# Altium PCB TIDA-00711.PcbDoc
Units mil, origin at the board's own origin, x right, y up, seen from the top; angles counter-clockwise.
Board outline 1889.76 x 1574.8 mil, 2 copper layers (Top Layer, Bottom Layer), stack 64.8 mil thick; 57 components, 26 nets, 126 pads, 115 vias.
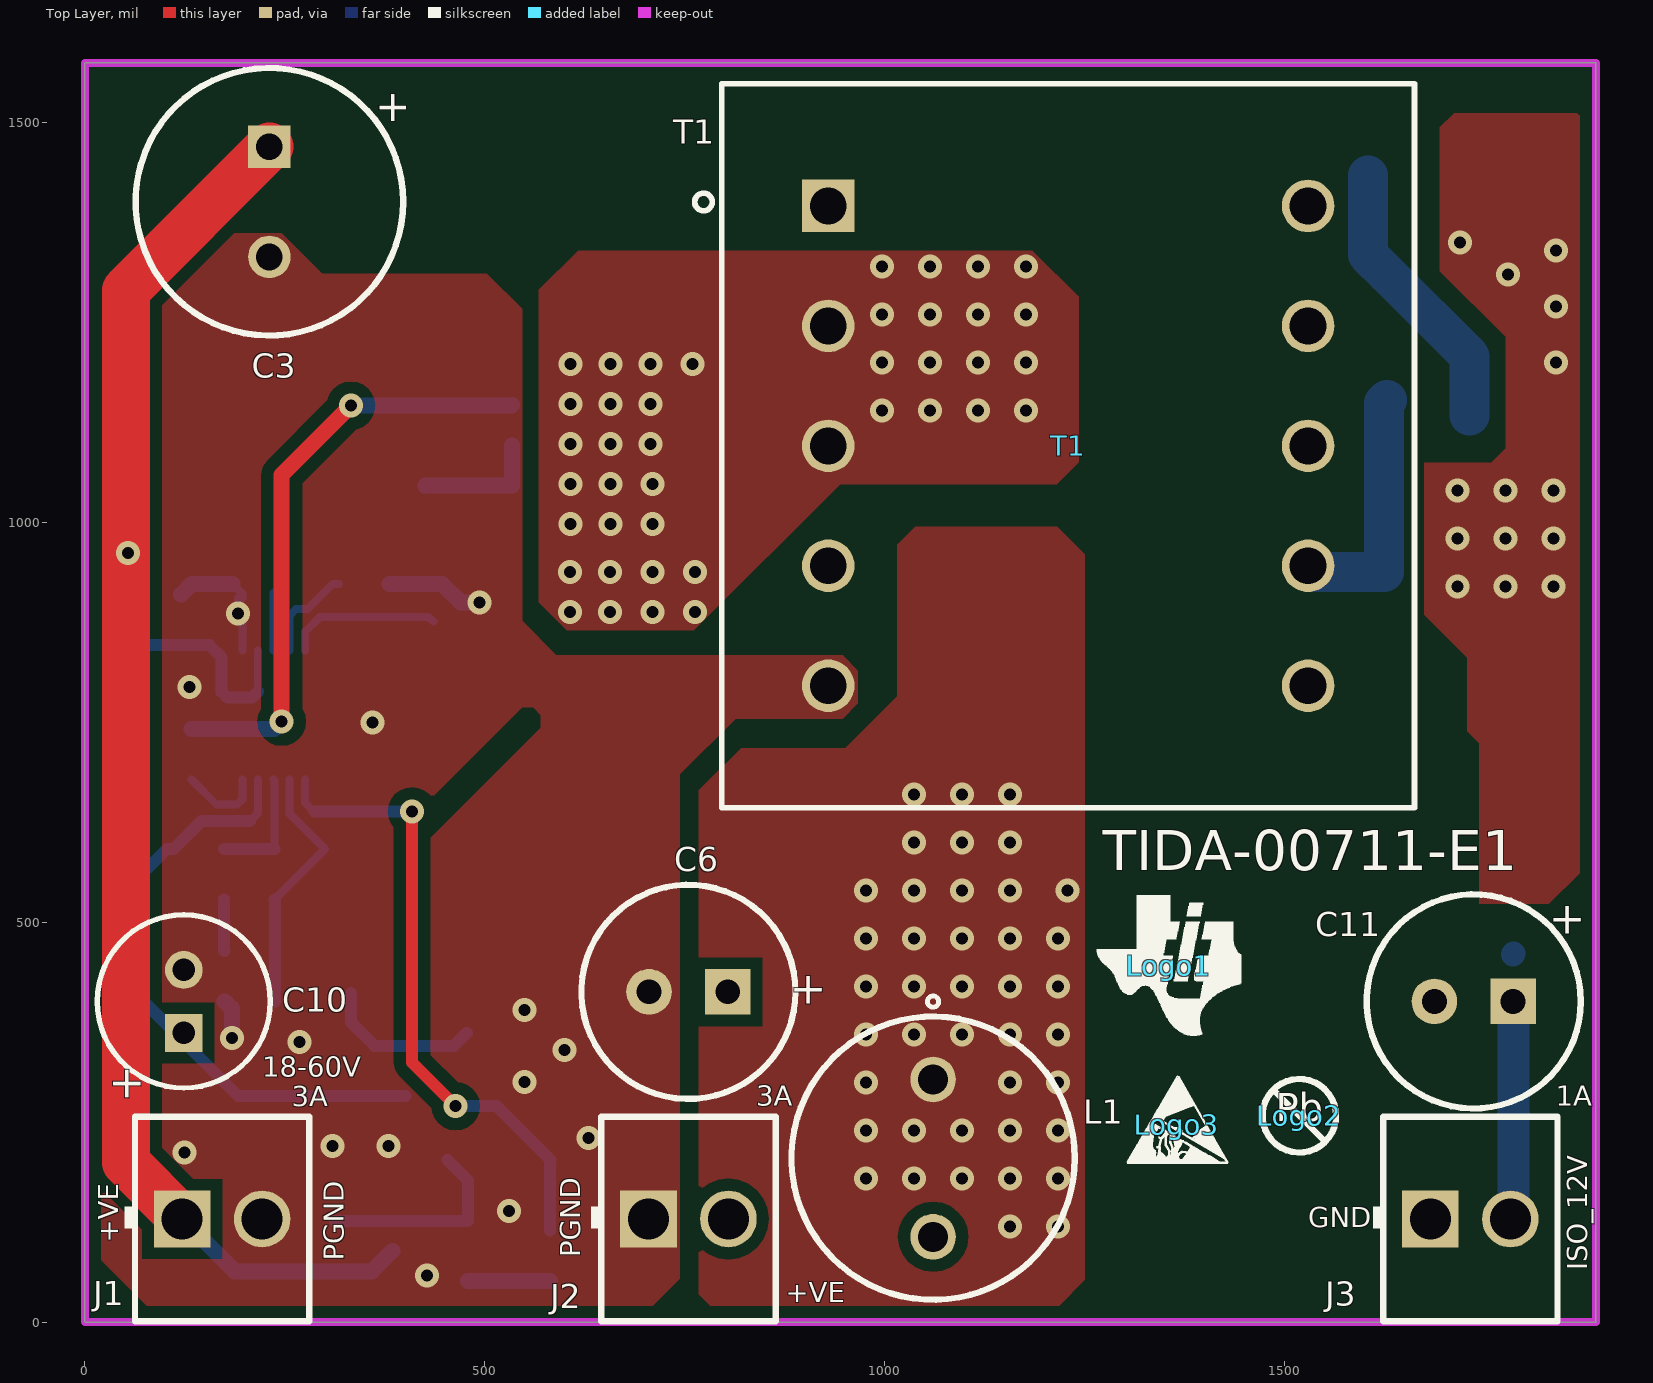
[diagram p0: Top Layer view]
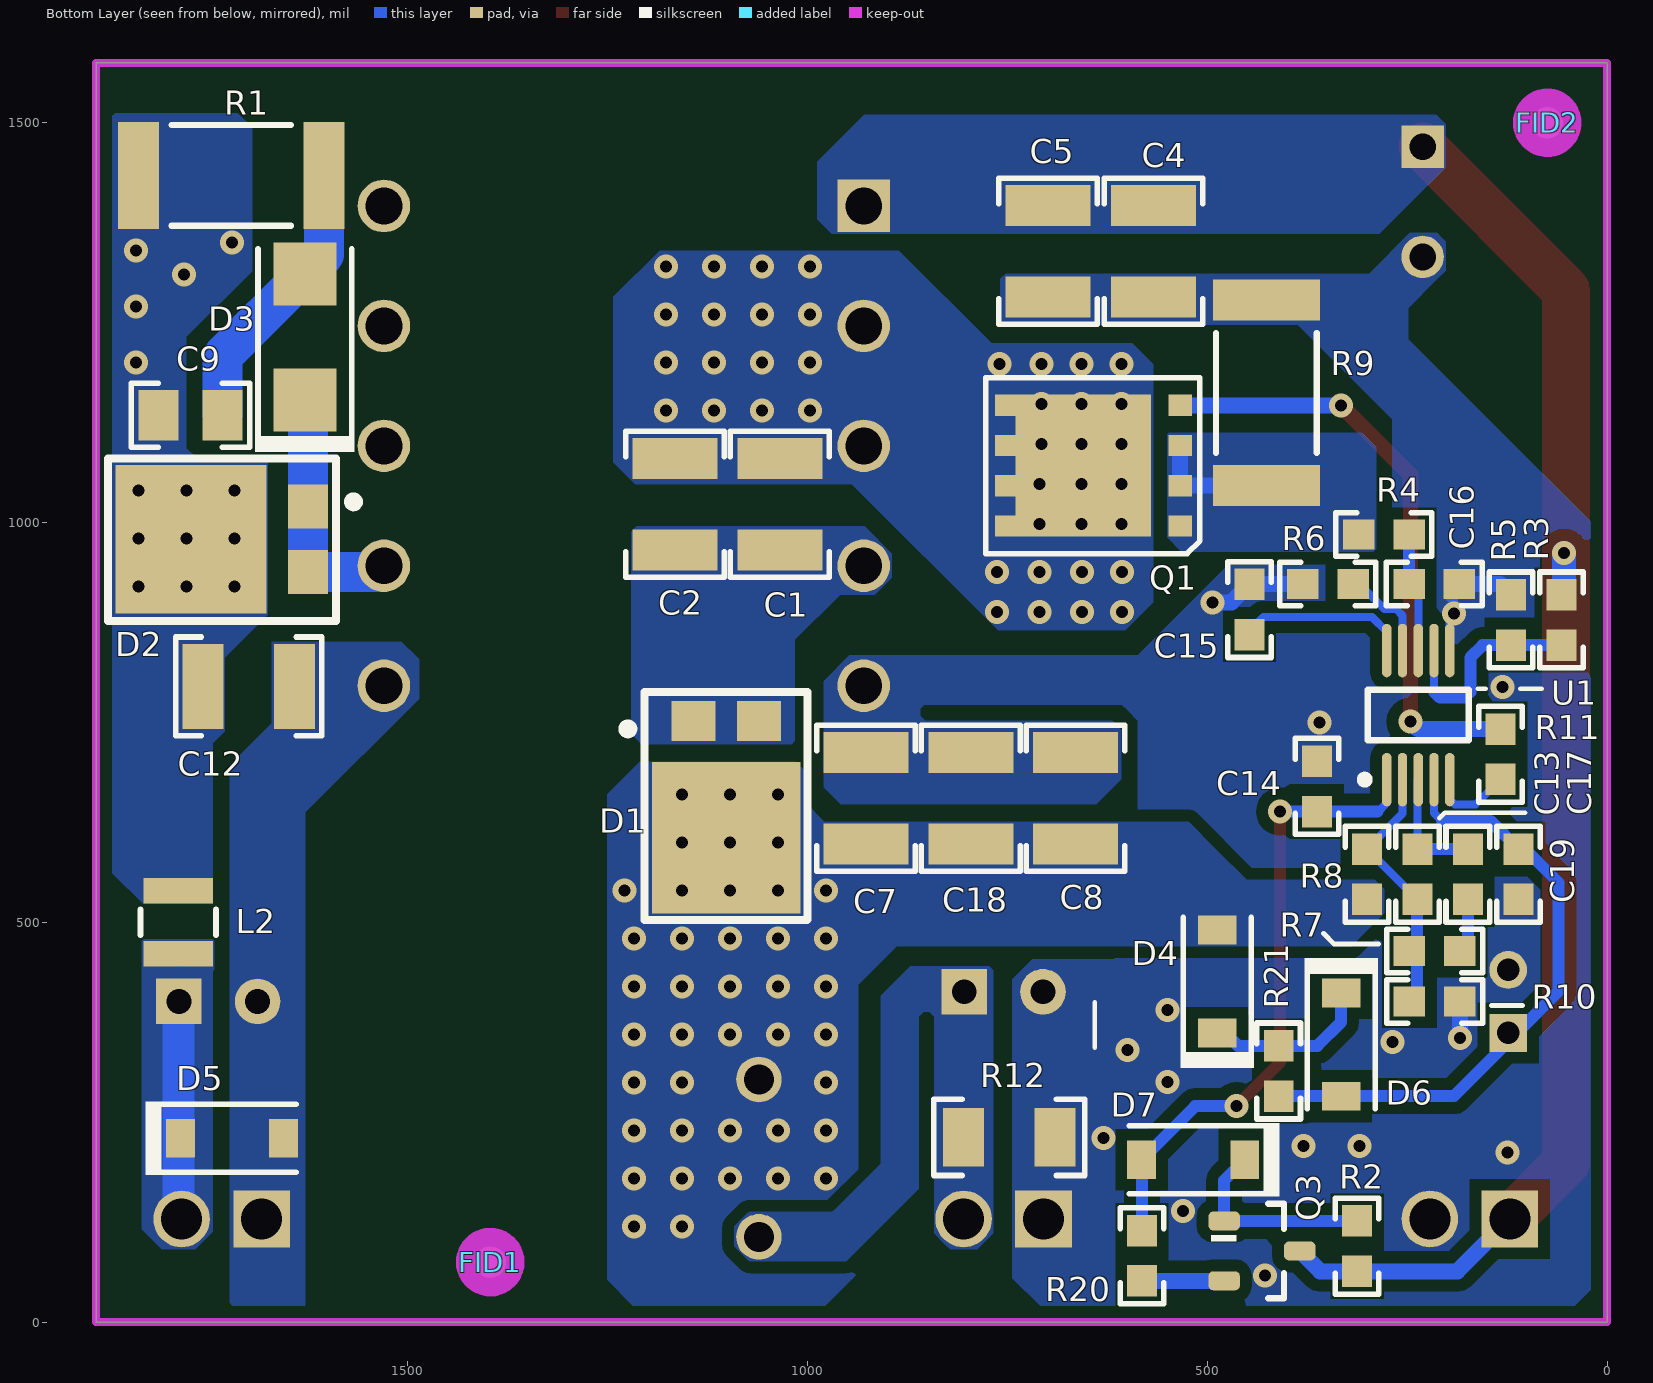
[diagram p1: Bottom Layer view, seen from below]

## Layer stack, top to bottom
Top Solder: solder mask 0.4, Solder Resist, Dk 3.5
Top Layer: signal copper 2.8
Dielectric1: core 59.2, FR-4 High Tg, Dk 4.8
Bottom Layer: signal copper 2.8
Bottom Solder: solder mask 0.4, Solder Resist, Dk 3.5

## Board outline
0,0 0,1574.8 1889.76,1574.8 1889.76,0

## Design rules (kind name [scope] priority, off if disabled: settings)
AcuteAngle [All] p1: minimum=4.50000000000000E+0001 checktracksonly=FALSE
AssemblyTestPointUsage [All] p1: valid=2
Clearance Clearance_Keepouts [((IsTrack Or IsArc) And Not InPoly) And IsFree and IsKeepOut vs ((IsTrack Or IsArc) And Not InPoly) And IsFree and IsKeepOut] p1: gap=20
Clearance Clearance_BoardEdge_MountingHoles [OnCopper and InComponentClass('Mounting Holes') vs IsKeepOut] p2: gap=40
Clearance Clearance_BoardEdge_Poly [OnCopper and InPoly vs IsKeepOut] p3: gap=15
Clearance Clearance_BoardEdge [OnCopper and Not InComponentClass('Logo') and not InComponentClass('FiducialMark') and not InRegion(1000,500,4000,800) and Not IsKeepout vs IsKeepOut] p4: gap=15
Clearance Clearance_Poly [InPolygon] p5: gap=15
Clearance [All] p6: gap=7.87
ComponentClearance ComponentClearance_MountingHoles_FiducialMarks [InComponentClass('Mounting Holes') vs InComponentClass('FiducialMark')] p1: gap=50 collisioncheckmode=3 verticalgap=10 showdistances=FALSE
ComponentClearance ComponentClearance_Shunt [InComponentClass('Header') vs InComponentClass('Shunt')] p2: gap=0 collisioncheckmode=3 verticalgap=0 showdistances=FALSE
ComponentClearance ComponentClearance_Logo [InComponentClass('Logo')] p3: gap=10 collisioncheckmode=3 verticalgap=10 showdistances=FALSE
ComponentClearance ComponentClearance_ScrewToNut [(HasFootprint('NY PMS 440 0025 PH')) vs (HasFootprint('Keystone_1902C'))] p4: gap=5 collisioncheckmode=3 verticalgap=10 showdistances=FALSE
ComponentClearance ComponentClearance_MountingHoles [InComponentClass('Mounting Holes')] p5: gap=200 collisioncheckmode=3 verticalgap=100000 showdistances=FALSE
ComponentClearance ComponentClearance_SmallPassives [HasFootprint('0201*') or HasFootprint('0402*') or HasFootprint('0508') or HasFootprint('0603*') or HasFootprint('0612') or HasFootprint('0805*') or HasFootprint('0815*') or HasFootprint('0830*') or HasFootprint('1206*') or HasFootprint('1210*') or HasFootprint('1808*') or HasFootprint('1812*') or HasFootprint('1825*') or HasFootprint('2010*') or HasFootprint('2220*') or HasFootprint('2225*') or HasFootprint('2512*') or HasFootprint('2728*') or HasFootprint('3518*') vs HasFootprint('0201*') or HasFootprint('0402*') or HasFootprint('0508') or HasFootprint('0603*') or HasFootprint('0612') or HasFootprint('0805*') or HasFootprint('0815*') or HasFootprint('0830*') or HasFootprint('1206*') or HasFootprint('1210*') or HasFootprint('1808*') or HasFootprint('1812*') or HasFootprint('1825*') or HasFootprint('2010*') or HasFootprint('2220*') or HasFootprint('2225*') or HasFootprint('2512*') or HasFootprint('2728*') or HasFootprint('3518*')] p6: gap=10 collisioncheckmode=3 verticalgap=10 showdistances=FALSE
ComponentClearance ComponentClearance_THtoSMT [IsThruComponent vs IsSMTComponent] p7: gap=20 collisioncheckmode=3 verticalgap=20 showdistances=FALSE
ComponentClearance ComponentClearance_THtoTH [IsThruComponent vs IsThruComponent] p8: gap=10 collisioncheckmode=3 verticalgap=10 showdistances=FALSE
ComponentClearance [All] p9: gap=10 collisioncheckmode=3 verticalgap=10 showdistances=FALSE
DiffPairsRouting [All] p1: maxlimit=100 minlimit=10 mostfreqgap=10 toplayer_minwidth=15 toplayer_maxwidth=15 toplayer_prefwidth=15 bottomlayer_minwidth=15 bottomlayer_maxwidth=15 bottomlayer_prefwidth=15 maxuncoupledlength=1000
FabricationTestPointUsage TestPointUsage [All] p1: valid=2 allowmultiple=FALSE
FabricationTestpoint Testpoint [All] p1: side=3 testpointundercomponent=TRUE minsize=40 maxsize=100 preferedsize=60 minholesize=0 maxholesize=40 preferedholesize=32 testpointgrid=1 allowsidetop=TRUE allowsidebottom=TRUE usegrid=TRUE gridtolerance=0.01
FanoutControl Fanout_LCC [IsLCC] p1: bgadir=Out bgaviamode=Centered fanoutstyle=Auto fanoutdirection=Alternating viagrid=1 // Fanout_LCC (Default Rule)
FanoutControl Fanout_BGA [IsBGA] p2: bgadir=Out bgaviamode=Centered fanoutstyle=Auto fanoutdirection=Alternating viagrid=1 // Fanout_BGA (Default Rule)
FanoutControl Fanout_Default [All] p4: bgadir=Out bgaviamode=Centered fanoutstyle=Auto fanoutdirection=Alternating viagrid=1 // Fanout_Default (Default Rule)
FanoutControl Fanout_Small [(CompPinCount < 5)] p5: bgadir=Out bgaviamode=Centered fanoutstyle=Auto fanoutdirection=OutThenIn viagrid=1 // Fanout_Small (Default Rule)
HoleSize [All] p1: absolutevalues=TRUE maxlimit=400 minlimit=8 maxpercent=80.000 minpercent=20.000
MinimumAnnularRing MinimumAnnularRing_ThermalPadVias [IsVia and InAnyComponent] p1: minimumring=5.91
MinimumAnnularRing [All] p2: minimumring=6
MinimumSolderMaskSliver MinimumSolderMaskSliver_Logo [InComponentClass('Logo') vs InComponentClass('Logo')] p1: minsoldermaskwidth=0.7
MinimumSolderMaskSliver [All] p2: minsoldermaskwidth=3.94
PlaneConnect [All] p1: planeconnectstyle=Relief reliefexpansion=10 reliefentries=4 reliefconductorwidth=10 reliefairgap=10
PolygonConnect [All] p1: connectstyle=Direct reliefconductorwidth=10 reliefentries=4 polygonreliefangle="90 Angle" airgapwidth=10
RoutingVias ThermalPadVias [IsVia and InAnyComponent] p1: holewidth=7.87 width=19.68 viastyle="Through Hole" minholewidth=7.87 minwidth=19.68 maxholewidth=12.99 maxwidth=23.62
RoutingVias [All] p2: holewidth=12 width=24 viastyle="Through Hole" minholewidth=7.87 minwidth=26 maxholewidth=40 maxwidth=65
SilkToBoardRegionClearance [Not ((IsComment or IsDesignator) And (Hide <> 'False')) and not InRegion(1000,500,4000,800)] p1:
SilkToSilkClearance SilkToSilkClearance_Pb-FreeLogo [(HasFootprint('Pb-Free_Overlay_Medium') OR HasFootprint('Pb-Free_Overlay_Small')) vs (HasFootprint('Pb-Free_Overlay_Medium') OR HasFootprint('Pb-Free_Overlay_Small'))] p1: silktosilkclearance=0
SilkToSilkClearance [All] p2: silktosilkclearance=4
SilkToSolderMaskClearance "Silk to Solder Mask Opening" [All] p1: minsilkscreentomaskgap=4 clearancetoexposedcopper=FALSE
SolderMaskExpansion [All] p1: expansion=1.97
UnpouredPolygon [All] p1: allowunpoured=FALSE
Width [All] p1: maxlimit=60 minlimit=6 preferedwidth=20 checkconnectedcopper=TRUE
14 further rules are at their usual default settings.

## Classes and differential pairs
component class Logo: Logo1
component class TIDA-00711_Hardware: FID1 FID2 Logo1 Logo2 Logo3 ZZ2 ZZ3 ZZ4
component class FiducialMark: FID1 FID2
component class AssemblyNote: ZZ2 ZZ3 ZZ4
component class TIDA-00711_Sheet1: C1 C2 C3 C4 C5 C6 C7 C8 C9 C10 C11 C12 C13 C14 C15 C16 C17 C18 C19 D1 D2 D3 D4 D5 D6 D7 J1 J2 J3 L1 L2 Q1 Q3 R1 R2 R3 R4 R5 R6 R7 R8 R9 R10 R11 R12 R20 R21 T1 U1

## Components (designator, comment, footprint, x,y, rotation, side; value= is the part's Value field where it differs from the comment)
C1 "GRM32ER71K475ME14L" 1210_270 1034.76,1022.8 r270 bottom
C2 "GRM32ER71K475ME14L" 1210_270 1165.76,1022.8 r270 bottom
C3 "UPM2A330MPD1TD" KZN_800x1500 230.76,1401 r270 top
C4 "GRM32ER71K475ME14L" 1210_270 567.26,1339.1 r270 bottom
C5 "GRM32ER71K475ME14L" 1210_270 699.26,1339.1 r270 bottom
C6 "EEU-FM1E101" FM_630x1120 754.85,413 r180 top
C7 "GRM32ER61E226KE15L" 1210_270 926.85,655 r90 bottom
C8 "GRM32ER61E226KE15L" 1210_270 664.85,655 r90 bottom
C9 "GRM21AR72E472KW01D" 0805_HV 1771.76,1134 r0 bottom
C10 "ESH476M025AC3AA" ML_500x500 123.76,401 r90 top
C11 "EEU-FM1E101" FM_630x1120 1736.96,401 r180 top
C12 "GRM32ER61E226KE15L" 1210_270 1698.85,795 r180 bottom
C13 "06035A2R2CAT2A" 0603 237.26,560 r270 bottom
C14 "06031C103JAT2A" 0603 362.76,670 r90 bottom
C15 "06033C104JAT2A" 0603 447.26,891.1 r90 bottom
C16 "GRM1885C2A101JA01D" 0603 216.26,923.1 r180 bottom
C17 "GRM1885C1H362JA01D" 0603 174.26,560 r90 bottom
C18 "GRM32ER61E226KE15L" 1210_270 795.85,655 r90 bottom
C19 "06033C104JAT2A" 0603 110.76,560 r270 bottom
D1 "FSV20150V" TO-277A 1101.76,679.8 r180 bottom
D2 "FSV12150V" TO-277A 1696.76,978.8 r270 bottom
D3 "B1100-13-F" SMA 1628.76,1232 r90 bottom
D4 "1N4148W-7-F" SOD-123 487.76,426 r90 bottom
D5 "MMSZ5245B-TP" SOD-123 1719.76,230 r180 bottom
D6 "MMSZ4678-TP" SOD-123 332.76,347 r270 bottom
D7 "MMSZ5231B-7-F" SOD-123 517.76,203 r0 bottom
FID1 "Fiducial" Fiducial10-20 1396.76,75 r90 bottom
FID2 "Fiducial" Fiducial10-20 75,1499.8 r90 bottom
J1 "OSTVN02A150" On-Shore_OSTVN02A150 171.76,129 r0 top
J2 "OSTVN02A150" On-Shore_OSTVN02A150 754.85,129 r0 top
J3 "OSTVN02A150" On-Shore_OSTVN02A150 1732.76,128.8 r0 top
L1 "RLB0912-2R2ML" RLB9012 1060.85,205 r270 top
L2 "CIG22E1R0MNE" 1008 1786.96,500 r270 bottom
Logo1 "Texas Instruments" TI_Symbol_Overlay_Small 1355.76,445.8 r0 top
Logo2 "Pb-Free Symbol" Pb-Free_Overlay_Small 1518.76,258 r0 top
Logo3 "ESD Susceptible" ESD_Overlay_Small 1365.76,247 r0 top
Q1 "CSD19531Q5A" TRANS_NexFET_Q5A 643.26,1071.1 r0 bottom
Q3 "BC846BLT1G" SOT-23 431.76,89 r180 bottom
R1 "CRM2512-JW-103ELF" 2512_084 1720.76,1434 r0 bottom
R2 "CRCW060322K1FKEA" 0603 312.76,95 r270 bottom
R3 "CRCW0603133KFKEA" 0603 57.26,878.1 r90 bottom
R4 "RC0603FR-07470RL" 0603 279.26,985.1 r0 bottom
R5 "CRCW060310K0FKEA" 0603 120.26,878.1 r270 bottom
R6 "RC0603FR-0721KL" 0603 349.26,923.1 r180 bottom
R7 "CRCW060320K0FKEA" 0603 215.76,464 r0 bottom
R8 "RC0603FR-0786K6L" 0603 300.26,560.1 r270 bottom
R9 "CSRN2512FK15L0" 2512 426.26,1162.1 r270 bottom
R10 "CRCW060310K0FKEA" 0603 215.76,401 r0 bottom
R11 "CRCW06034R99FKEA" 0603 133.26,710.1 r90 bottom
R12 "RNCP1206FTD475R" 1206 747.76,231 r0 bottom
R20 "CRCW06031K82FKEA" 0603 581.76,83 r270 bottom
R21 "CRCW0603100RFKEA" 0603 410.76,314 r90 bottom
T1 "750343373" WE_750343373 1229.76,1095.8 r0 top
U1 "LM5020MM-1/NOPB" MUB10A_N 236.26,759.1 r90 bottom
ZZ2 "These assemblies are ESD sensitive, ESD precautions shall be observed." AssemblyNote 146.96,1923.6 r0 top
ZZ3 "These assemblies must be clean and free from flux and all contaminants. Use of no clean flux is not acceptable." AssemblyNote 146.96,1835.05 r0 top
ZZ4 "These assemblies must comply with workmanship standards IPC-A-610 Class 2, unless otherwise specified." AssemblyNote 146.96,1746.49 r0 top

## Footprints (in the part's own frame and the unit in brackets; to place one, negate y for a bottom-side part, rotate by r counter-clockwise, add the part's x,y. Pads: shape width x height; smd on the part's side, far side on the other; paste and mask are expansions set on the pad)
0603 [mm] "0603 from SM-752 data"
  rect 1x0.95 smd: 1(-0.8,0) 2(0.8,0)
  silkscreen extent -1.52,-0.69 1.52,0.69, body extent -0.87,-0.47 0.87,0.47, height 1
0805_HV [mil] "0805 with 30mil clearance between pads"
  rect 50x63 smd: 1(-40,0) 2(40,0)
  silkscreen extent -74,-40 74,40, body extent -43,-29 43,29, height 57
1008 [mm] "SMD, Body 2.5x2mm, Height 1.2mm"
  rect 0.8x2.2 smd: 1(-1,0) 2(1,0)
  silkscreen extent -0.4,-1.2 0.4,1.2, body extent -1.35,-1.1 1.35,1.1, height 1.2
1206 [mm] "1206 from SM-752 data"
  rect 1.3x1.85 smd: 1(-1.45,0) 2(1.45,0)
  silkscreen extent -2.4,-1.21 2.4,1.21, body extent -1.7,-0.9 1.7,0.9, height 1.35
1210_270 [mm] "1210"
  rect 1.3x2.7 smd: 1(-1.45,0) 2(1.45,0)
  silkscreen extent -2.32,-1.57 2.32,1.57, body extent -1.7,-1.35 1.7,1.35, height 2.7
2512 [mm] "Chip Resistor, Body 6.3x3.2mm, IPC Medium Density"
  rect 1.3x3.4 smd: 1(-2.95,0) 2(2.95,0)
  silkscreen extent -1.9,-1.6 1.9,1.6, body extent -3.22,-1.67 3.22,1.67, height 0.71
2512_084 [mm] "Chip Resistor, Body 6.3x3.2mm"
  rect 1.3x3.4 smd: 1(-2.95,0) 2(2.95,0)
  silkscreen extent -1.9,-1.6 1.9,1.6, body extent -3.22,-1.67 3.22,1.67, height 0.84
AssemblyNote [mil] "Assembly Note"
ESD_Overlay_Small [mil]
  silkscreen extent -62,-48 64,61
Fiducial10-20 [mm]
  round 1 smd mask+0.5: 1(0,0)
  Top Layer keep-out circle w1.178: c0,0 r0.5
FM_630x1120 [mm] "PANASONIC"
  rect 1.45x1.45 hole 0.787: 1(-1.25,0)
  round 1.45 hole 0.787: 2(1.25,0)
  silkscreen extent -3.4,-3.4 3.4,3.4, body extent -3.37,-3.39 3.4,3.39, height 12.71
KZN_800x1500 [mm] "TH, 2-Leads, Dia 8mm, Pin Spacing 3.5mm"
  rect 1.35x1.35 hole 0.85: 1(-1.75,0)
  round 1.35 hole 0.85: 2(1.75,0)
  silkscreen extent -4.25,-4.25 4.25,4.25, body extent -4.22,-4.24 4.24,4.24, height 16.51
ML_500x500 [mm] "Rubycon"
  rect 1.2x1.2 hole 0.711: 1(-1,0)
  round 1.2 hole 0.711: 2(1,0)
  silkscreen extent -2.75,-2.75 2.75,2.75, body extent -2.73,-2.75 2.75,2.75, height 6.51
MUB10A_N [mm] "TSSOP, 10-Leads, Body 3x3mm, Pitch 0.5mm, IPC Medium Density"
  oval 1.7x0.3 smd: 1(-2.05,1) 2(-2.05,0.5) 3(-2.05,0) 4(-2.05,-0.5) 5(-2.05,-1) 6(2.05,-1) 7(2.05,-0.5) 8(2.05,0) 9(2.05,0.5) 10(2.05,1)
  silkscreen extent -2.17,-1.6 0.8,1.83, body extent -1.6,-1.6 1.6,1.6, height 1.09
On-Shore_OSTVN02A150 [mm] "Terminal Block, 2.54mm, 2-pole, Brass, TH"
  rect 1.8x1.8 hole 1.3: 1(-1.27,0)
  round 1.8 hole 1.3: 2(1.27,0)
  silkscreen extent -3.1,-3.25 2.77,3.25, body extent -2.77,-3.25 2.77,3.25, height 8.51
Pb-Free_Overlay_Small [mil]
  silkscreen extent -46,-46 46,46
RLB9012 [mm] "TH, 2-Leads, Dia 9mm, Pin Spacing 5mm"
  round 1.45 hole 0.95: 1(-2.5,0) 2(2.5,0)
  silkscreen extent -4.5,-4.5 4.5,4.5, body extent -4.6,-4.6 4.6,4.6, height 11
SMA [mm] "Molded Diode, 2-Leads, Body 4.3x2.6mm, IPC Medium Density, based on OnSemi component dimensions and land pattern"
  rect 2x2 smd: 1(-2,0) 2(2,0)
  silkscreen extent -3.66,-1.57 2.79,1.57, body extent -2.6,-1.3 2.6,1.3, height 2.42
SOD-123 [mm] "On Semi recommended land pattern"
  rect 0.915x1.22 smd: 1(-1.637,0) 2(1.637,0)
  silkscreen extent -2.74,-1.17 2.03,1.17, body extent -1.93,-0.9 1.93,0.9, height 1.35
SOT-23 [mm] "SOT23, 3-Leads, Body 2.9x1.3mm, Pitch 0.95mm, Lead Span 2.5mm, IPC Medium Density"
  rrect50% 1x0.6 smd: 1(-1.2,0.95) 2(-1.2,-0.95) 3(1.2,0)
  silkscreen extent -1.63,-1.5 0.7,1.5, body extent -1.16,-1.45 1.21,1.45, height 1
TI_Symbol_Overlay_Small [mil]
  silkscreen extent -90,-88 91,88
TO-277A [mm] "Vishay"
  rect 1.4x1.27 smd: 1(-1.04,1.83) 2(1.04,1.83)
  rect 4.72x4.8 smd: 3(0,-1.883)
  silkscreen extent -3.27,1.42 -2.97,1.72, body extent -2.35,-4.2 2.4,2.45, height 1.2
TRANS_NexFET_Q5A [mm] "TI recommended land pattern (nominal) M0139-01"
  rect 0.75x0.675 smd paste-0.1 mask+0.051: 1(-2.776,1.917) 2(-2.776,0.639) 3(-2.776,-0.639) 4(-2.776,-1.917)
  rect 0.655x0.675 smd paste-0.1 mask+0.051: 5(2.776,-1.917) 6(2.776,-0.639) 7(2.776,0.639) 8(2.776,1.917)
  rect 4.295x4.51 smd paste-2.2 mask+0.051: 9(0.301,0)
  silkscreen extent -3.4,-2.8 3.4,2.8, body extent -3.05,-2.5 3.05,2.5, height 1.11
WE_750343373 [mm] "TRANSFOERMER, TH, 10-PIN"
  rect 1.67x1.67 / inner round 1.67 / far side rect 1.67x1.67 hole 1.17: 1(-7.62,7.62)
  round 1.67 hole 1.17: 2(-7.62,3.81) 3(-7.62,0) 4(-7.62,-3.81) 5(-7.62,-7.62) 6(7.62,-7.62) 7(7.62,-3.81) 8(7.62,0) 9(7.62,3.81) 10(7.62,7.62)
  silkscreen extent -11.86,-11.5 11,11.5, body extent -11,-11.5 11,11.5, height 17.53

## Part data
C1 C2 C4 C5: library part GRM32ER71K475KE14L, "4.7µF ±20% 80V Ceramic Capacitor X7R 1210 (3225 Metric)"
C3: library part EKZN101ELL470MH15D, "33µF 100V Aluminum Capacitors Radial, Can 3000 Hrs @ 105°C"
C6 C11: "CAP, AL, 100 µF, 25 V, +/- 20%, 0.13 ohm, TH"
C7 C8 C12 C18: "CAP, CERM, 22 µF, 25 V, +/- 10%, X5R, 1210"
C9: "CAP, CERM, 4700 pF, 250 V, +/- 10%, X7R, 0805"
C10: library part 25ML22MEFC5X5, "47µF 25V Aluminum Capacitors Radial, Can 2000 Hrs @ 105°C"
C13: "CAP, CERM, 2.2 pF, 50 V, +/- 11%, C0G/NP0, 0603"
C14: "CAP, CERM, 0.01 µF, 100 V, +/- 5%, X7R, 0603"
C15 C19: "CAP, CERM, 0.1 µF, 25 V, +/- 5%, X7R, 0603"
C16: "CAP, CERM, 100 pF, 100 V, +/- 5%, C0G/NP0, 0603"
C17: "CAP, CERM, 3600 pF, 50 V, +/- 5%, C0G/NP0, 0603"
D1: library part FSV12100V, "Diode Schottky 150V 20A Surface Mount TO-277-3"
D2: library part FSV12100V, "Diode Schottky 150V 12A Surface Mount TO-277-3"
D3: "Diode, Schottky, 100 V, 1 A, SMA"
D4: "Diode, Ultrafast, 100 V, 0.15 A, SOD-123"
D5: library part BZT52B16-HE3-08, "Zener Diode 15V 500mW ±5% Surface Mount SOD-123"
D6: library part BZT52B9V1-HE3-08, "Zener Diode 1.8V 500mW ±5% Surface Mount SOD-123"
D7: library part BZT52C5V1-G3-08, "Zener Diode 5.1V 500mW ±5% Surface Mount SOD-123"
FID1 FID2: "Fiducial mark.  There is nothing to buy or mount."
J1 J2 J3: "Terminal Block, 2.54mm, 2x1, Brass, TH"
L1: library part DFE252012P-2R2M=P2, "Inductor, Shielded, 2.2 µH, 2.6 A, 0.07 ohm, SMD"
L2: "Inductor, Multilayer, 1 µH, 2.2 A, 0.048 ohm, SMD"
Logo1: library part TI_Logo, "Texas Instrument Corporate Signature"
Logo2: library part Pb-Free
Logo3: library part ESD_Susceptible, "ESD Susceptible Symbol"
Q1: "MOSFET, N-CH, 100 V, 16 A, SON 5x6mm"
Q3: library part "BC846BLT1G, ON Semiconductor", "Transistor, NPN, 65 V, 0.1 A, SOT-23"
R1: library part HVCB2512FDD10K0, "RES SMD 10K OHM 5% 2W 2512"
R2: "RES, 22.1 k, 1%, 0.1 W, 0603"
R3: "RES, 133 k, 1%, 0.1 W, 0603"
R4: "RES, 470, 1%, 0.1 W, 0603"
R5 R10: "RES, 10.0 k, 1%, 0.1 W, 0603"
R6: "RES, 21.0 k, 1%, 0.1 W, 0603"
R7: "RES, 20.0 k, 1%, 0.1 W, 0603"
R8: "RES, 86.6 k, 1%, 0.1 W, 0603"
R9: "RES, 0.015, 1%, 2 W, 2512"
R11: "RES, 4.99, 1%, 0.1 W, 0603"
R12: library part CRCW1206475RFKEA, "RES SMD 475 OHM 1% 1/2W 1206"
R20: "RES, 1.82 k, 1%, 0.1 W, 0603"
R21: "RES, 100, 1%, 0.1 W, 0603"
T1: library part G154056LF, "Transformer, 15µH, TH"
U1: "100V Current Mode PWM Controller, 10-pin MSOP, Pb-Free"
ZZ2 ZZ3 ZZ4: library part AssemblyNote

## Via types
v1: diameter 30, hole 15, Top Layer to Bottom Layer, 115 vias

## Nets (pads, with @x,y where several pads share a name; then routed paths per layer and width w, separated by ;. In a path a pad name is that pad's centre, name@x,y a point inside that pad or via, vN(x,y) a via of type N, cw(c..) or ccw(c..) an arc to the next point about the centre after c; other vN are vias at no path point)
12V: C7.1 C8.1 C18.1 D1.3 D4.2 L1.1 R8.2
  other v1: 1156.76,119.8 1216.76,119.8 976.76,179.8 1036.76,179.8 1096.76,179.8 1156.76,179.8 1216.76,179.8 976.76,239.8 1036.76,239.8 1096.76,239.8 1156.76,239.8 1216.76,239.8 976.76,299.8 1156.76,299.8 1216.76,299.8 976.76,359.8 1036.76,359.8 1096.76,359.8 1156.76,359.8 1216.76,359.8 976.76,419.8 1036.76,419.8 1096.76,419.8 1156.76,419.8 1216.76,419.8 976.76,479.8 1036.76,479.8 1096.76,479.8 1156.76,479.8 1216.76,479.8 976.76,539.8 1036.76,539.8 1096.76,539.8 1156.76,539.8 1228.76,540 1036.76,599.8 1096.76,599.8 1156.76,599.8 1036.76,659.8 1096.76,659.8 1156.76,659.8
GND: C11.2 C12.2 D5.2 J3.1 T1.6
ISO_12V: C11.1 D5.1 J3.2 L2.2 | length 273.4
  Bottom Layer w30: L2.2@1786.17,459.84 L2.2
  Bottom Layer w40: C11.1 1786.96,400.21 J3.2@1786.96,129
NetC1_1: C1.1 C2.1 Q1.5 Q1.6 Q1.7 Q1.8 Q1.9 T1.2 T1.3
  other v1: 606.76,888 656.76,888 709.78,888 762.8,888 606.76,938 656.76,938 709.78,938 762.8,938 607.16,997.91 657.16,997.91 710.17,997.91 607.16,1047.91 657.16,1047.91 710.17,1047.91 607.16,1097.91 657.16,1097.91 707.16,1097.91 996.85,1140 1056.85,1140 1116.85,1140 1176.85,1140 607.16,1147.91 657.16,1147.91 707.16,1147.91 607.16,1197.91 657.16,1197.91 707.16,1197.91 760.17,1197.91 996.85,1200 1056.85,1200 1116.85,1200 1176.85,1200 996.85,1260 1056.85,1260 1116.85,1260 1176.85,1260 996.85,1320 1056.85,1320 1116.85,1320 1176.85,1320
NetC1_2: C1.2 C2.2 D1.1 D1.2 T1.4
NetC3_1: C3.1 C4.1 C5.1 J1.1 Q3.3 R2.2 R3.2 T1.1 | length 1798.7
  Top Layer w60: J1.1 51.27,199.5 51.27,1290.4 C3.1
  Bottom Layer w20: J1.1 187.26,63.5 R2.2 359.02,63.5 Q3.3
  Bottom Layer w30: v1(53.76,962) 53.76,913.09 R3.2
NetC6_1: C6.1 J2.2 L1.2 R12.2
NetC9_1: C9.1 D3.2 R1.1 | length 352.7
  Bottom Layer w50: R1.1 1604.62,1334.88 D3.2 1731.76,1207.74 C9.1
NetC9_2: C9.2 C12.1 D2.3 L2.1 R1.2
  other v1: 1716.76,919.8 1776.76,919.8 1836.76,919.8 1716.76,979.8 1776.76,979.8 1836.76,979.8 1716.76,1039.8 1776.76,1039.8 1836.76,1039.8 1839.76,1200 1839.76,1270 1779.76,1310 1839.76,1340 1719.76,1350
NetC10_1: C10.1 C19.1 D6.2 R21.1 U1.4 | length 763.7
  Bottom Layer w10: 206.39,626.63 216.57,636.81 U1.4
  Bottom Layer w15: 206.39,626.63 145.89,626.63 C19.1 102.5,591.5 61,550 61,413.39 191.86,282.53 D6.2@322.76,282.53 ; D6.2@322.79,282.5 R21.1@400.76,282.5
NetC13_1: C13.1 C17.2 U1.3 | length 150.2
  Bottom Layer w10: U1.3 237.16,677.49 237.16,591.69 C13.1@237.26,591.6
  Bottom Layer w15: C17.2@174.26,591.6 C13.1@237.26,591.6
NetC13_2: C13.2 R7.2 R8.1 R10.2 U1.2 | length 322
  Bottom Layer w10: C13.2@237.26,528.61 R8.1 255.94,635.91 U1.2
  Bottom Layer w15: C13.2@237.26,528.61 237.75,528.11 237.75,464.1 R10.2@237.75,401.1
NetC14_1: C14.1 D7.2 R20.1 U1.1 | length 793
  Top Layer w15: v1(409.27,638.5) 409.27,324.5 v1(463.76,270)
  Bottom Layer w10: U1.1 275.63,649.13 286.76,638
  Bottom Layer w15: 287.27,638.5 C14.1 v1(409.27,638.5) ; v1(463.76,270) 515.23,270 D7.2 581.76,202.53 R20.1
NetC15_1: C15.1 U1.10 | length 193.8
  Bottom Layer w10: U1.10 275.63,863.36 294.17,881.91 429.96,881.91 C15.1@435.76,876.1
NetC16_1: C16.1 R4.1 U1.8 | length 150.1
  Bottom Layer w10: U1.8 236.26,911.61 C16.1
  Bottom Layer w15: C16.1 R4.1
NetC17_1: C17.1 R7.1 | length 64.7
  Bottom Layer w15: C17.1@174.26,528.61 174.26,464.61 R7.1@174.76,464.1
NetD2_1: D2.1 D2.2 D3.1 T1.7 | length 315.3
  Bottom Layer w50: T1.7 1537.71,937.86 D2.2 D2.1 1624.72,1149.21 D3.1
NetD4_1: D4.1 D6.1 R21.2 | length 200.2
  Bottom Layer w15: D6.1 332.76,375.24 362.5,345.5 461.73,345.5 D4.1@477.76,361.53
NetD7_1: D7.1 Q3.1 R2.1 | length 253.5
  Bottom Layer w15: R2.1 478.91,126.5 Q3.1 479.01,177.29 D7.1
NetQ1_1: Q1.1 Q1.2 Q1.3 R4.2 R9.2 | length 158.7
  Bottom Layer w20: R9.2@425.75,1045.46 R9.2 Q1.2@533.93,1045.96 ; Q1.2 Q1.3
NetQ1_4: Q1.4 R11.2 | length 749.2
  Top Layer w20: v1(246.17,750.91) 246.17,1059.41 v1(332.76,1146)
  Bottom Layer w20: R11.2 236.87,741.6 v1(246.17,750.91) ; v1(332.76,1146) 533.36,1146 Q1.4
NetQ3_2: Q3.2 R20.2 | length 102.8
  Bottom Layer w20: Q3.2 581.67,51.6 R20.2
NetR3_1: R3.1 R5.2 U1.7 | length 266.1
  Bottom Layer w10: 216.57,788.31 U1.7
  Bottom Layer w15: R3.1 R5.2 155.75,846.61 171.17,831.19 171.17,788.19 178.26,781.1 209.37,781.1 216.57,788.31
NetR6_2: R6.2 U1.9 | length 122
  Bottom Layer w10: U1.9 255.94,883.68 263.79,891.53 278.52,891.53 310.09,923.1 R6.2
NetR11_1: R11.1 U1.5 | length 104.2
  Bottom Layer w10: R11.1 164.87,647 190.27,647 196.89,653.62 U1.5
PGND: C3.2 C4.2 C5.2 C6.2 C7.2 C8.2 C10.2 C14.2 C15.2 C16.2 C18.2 C19.2 J1.2 J2.1 R5.1 R6.1 R9.1 R10.1 R12.1 T1.5 U1.6 | length 333.1
  Bottom Layer w10: C16.2 196.89,910.98 C16.2@196.89,905.42 ; C16.2@191.34,905.42 v1(191.34,885.91) 196.89,880.35 U1.6
  Bottom Layer w20: R5.1 133.76,923.1 C16.2 ; R10.1@174.76,401.1 183.76,392.1 v1(183.76,355) ; R6.1 446.75,923.1 C15.2 469.86,900 v1(493.76,900)
  other v1: 427.76,58 530.76,139 124.76,212 309.76,220 379.76,220 629.76,230 549.76,300 599.76,340 268.76,350 549.76,390 359.76,750 130.76,794
pads on no net: FID1.1 FID2.1 T1.8 T1.9 T1.10

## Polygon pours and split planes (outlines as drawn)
NetC9_2 on Bottom Layer "Bottom Layer-No Net" (solid, remove dead copper, pour order 37): 1694.76,1493.94 1694.76,1314 1776.76,1232 1776.85,1231.91 1776.85,1093 1758.65,1074.8 1674.85,1074.8 1674.85,884.72 1728.76,830.8 1728.76,738.8 1743.85,723.72 1743.65,723.52 1743.65,523 1830.85,523 1869.37,561.52 1889.76,581.91 1889.76,632 1889.76,1488.07 1865.84,1512 1712.82,1512
PGND on Bottom Layer "Bottom Layer-No Net" (solid, remove dead copper, pour order 32): 0,137 0,60.76 60.76,0 688.76,0 743.76,55 743.76,306 743.76,429 718.76,454 616.76,454 586.76,484 586.76,752 599.76,765 606.76,772 818.76,772 853.76,772 858.76,767 872.76,767 872.76,820 858.76,834 793.76,834 586.76,834 473.76,947 458.76,947 292.65,947 268.76,970.88 268.76,1129 386.76,1247 456.76,1247 751.76,1247 757.76,1253 758.76,1254 758.76,1279 758.76,1304.64 752.41,1311 733.76,1311 297.76,1311 246.76,1362 212.76,1362 206.76,1356 201.76,1351 201.76,1341 201.76,1315 214.76,1302 248.76,1268 248.76,1229 -0.24,980
12V on Bottom Layer "M9 Title Sheet-No Net" (solid, remove dead copper, pour order 19): 1250.76,52.8 1197.96,0 1117.76,0 998.57,0 941.09,57.48 936.76,61.8 936.76,215 936.76,421.8 888.57,470 319.76,470 278.76,511 278.76,537 278.76,553 389.76,553 450.76,553 523.76,626 978.85,626 1002.76,649.91 1002.76,688.61 1015.15,701 1209.57,701 1250.76,659.8
NetC6_1 on Bottom Layer "Bottom Layer-No Net" (solid, remove dead copper, pour order 31): 767.76,111.09 767.76,439.91 772.85,445 832.85,445 871.57,445 908.57,408 908.57,198 968.82,137.75 1073.65,137.92 1091.76,119.8 1091.76,94.8 1072.76,75.8 951.76,75.8 860.76,166.8 860.76,381.8 854.76,387.8 847.76,387.8 841.76,381.8 841.76,110.8 828.76,97.8 821.76,90.8 799.76,90.8 788.05,90.8
GND on Bottom Layer "M9 Title Sheet-No Net" (solid, remove dead copper, pour order 18): 1652.85,851 1507.85,851 1489.85,833 1485.85,829 1485.85,794 1485.85,779.72 1627.9,637.66 1627.91,142 1627.91,20.73 1647.59,1.05 1706.9,1.05 1722.76,16.91 1722.76,696.09 1669.85,749 1669.85,851
NetQ1_1 on Bottom Layer "M9 Title Sheet-No Net" (solid, remove dead copper, pour order 21): 288.76,1094 288.76,963.41 532.45,963.41 550.45,981.41 550.45,1098.41 550.45,1110.41 548.45,1112.41 520.45,1112.41 307.17,1112.41
NetC1_1 on Bottom Layer "M9 Title Sheet-No Net" (solid, remove dead copper, pour order 22): 602.76,865 761.76,865 944.57,1047.8 1215.65,1047.8 1228.85,1061 1242.85,1075 1242.85,1282 1184.85,1340 885.76,1340 769.76,1224 593.76,1224 567.76,1198 567.76,900
NetC1_2 on Bottom Layer "M9 Title Sheet-No Net" (solid, remove dead copper, pour order 23): 894.76,961 894.76,930.8 915.76,909.8 959.05,909.8 1015.76,853.09 1015.76,727.09 1020.05,722.8 1207.65,722.8 1220.76,735.91 1220.76,988.09 1213.85,995 928.76,995
PGND on Bottom Layer "M9 Title Sheet-No Net" (solid, remove dead copper, pour order 24): 607.85,678.72 638.76,647.8 958.76,647.8 980,669.04 980,801.57 947.57,834 897.57,834 858.76,834 858.76,758 852.76,752 662.85,752 618.85,752 607.85,741 607.85,728
NetC3_1 on Bottom Layer "M9 Title Sheet-No Net" (solid, remove dead copper, pour order 25): 284.96,1360.8 201.76,1444 201.76,1498 213.76,1510 433.85,1510 928.85,1510 987.85,1451 987.85,1378.89 969.76,1360.8
ISO_12V on Bottom Layer "Bottom Layer-No Net" (solid, remove dead copper, pour order 20): 1741.76,475.8 1741.76,440.8 1743.76,438.8 1743.76,112.8 1765.76,90.8 1807.76,90.8 1832.76,115.8 1832.76,135.8 1832.76,446.8 1832.76,476.31 1830.27,478.8 1758.76,478.8 1743.76,478.8 1741.76,476.8
NetC9_2 on Top Layer "Bottom Layer-No Net" (solid, remove dead copper, pour order 37): 1694.76,1493.94 1694.76,1314 1776.76,1232 1776.85,1231.91 1776.85,1093 1758.65,1074.8 1674.85,1074.8 1674.85,884.72 1728.76,830.8 1728.76,738.8 1743.85,723.72 1743.65,723.52 1743.65,523 1830.85,523 1869.37,561.52 1889.76,581.91 1889.76,632 1889.76,1488.07 1865.84,1512 1712.82,1512
NetC1_1 on Top Layer "Bottom Layer-No Net" (solid, remove dead copper, pour order 28): 602.76,865 761.76,865 944.57,1047.8 1005.76,1047.8 1215.65,1047.8 1242.85,1075 1242.85,1282 1184.85,1340 616.76,1340 567.76,1291 567.76,900
PGND on Top Layer "Bottom Layer-No Net" (solid, remove dead copper, pour order 29): 0.16,97.6 97.96,-0.2 689.57,-0.2 743.76,54 743.76,684.8 813.76,754.8 947.76,754.8 966.76,773.8 966.76,814.8 947.57,834 589.76,834 546.76,877 546.76,1267 502.76,1311 296.76,1311 264.76,1343 245.96,1361.8 23.06,1361.8 -1.35,1337.39
12V on Top Layer "Bottom Layer-No Net" (solid, remove dead copper, pour order 30): 767.76,664.8 767.76,35.05 801.76,1.05 1199.01,1.05 1250.76,52.8 1250.76,960.04 1216,994.8 1038.76,994.8 1015.76,971.8 1015.76,782.8 950.76,717.8 820.76,717.8

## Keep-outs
Keep-Out Layer:
  the board outline again, w10
  text ".Layer_Name" at 576.96,-1164 h60

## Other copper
Top Layer:
  pour cut-out: 432.21,605.44 569.76,743 569.76,759 560.76,768 546.76,768 408.21,629.44
  text ".Layer_Name" at 576.96,-1164 h60
Bottom Layer:
  text ".Layer_Name" at 576.96,-1164 h60

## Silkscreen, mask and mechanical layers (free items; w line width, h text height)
Top Overlay:
  circle w6: c1060.76,400.8 r7.07
  text "TIDA-00711-E1" at 1272.76,564.8 h50
  text "18-60V" at 221.76,307 h25
  text "3A" at 258.76,270 h25
  text "3A" at 839.76,270.8 h25
  text "1A" at 1839.76,270.8 h25
  text "GND" at 1529.76,118.8 h25
  text "+VE" at 41.76,99 h25 r90
  text "PGND" at 619.76,81 h25 r90
  text "PGND" at 323.76,77 h25 r90
  text "ISO_12V" at 1878.76,64.8 h25 r90
  text "+VE" at 876.76,24.8 h25
  text ".Layer_Name" at 576.96,-1164 h60
Bottom Overlay:
  lines w6: 81.76,792 108.76,792 ; 102.76,636.91 150.17,636.91 200.86,636.91 202.86,636.91 209.76,630 ; 106,395.91 144.76,395.91 ; 151.76,792 161.76,792 ; 285.76,473 341.76,473 354.76,486 ; 640.76,343 640.76,400
  lines w10: 1000.36,503.49 1000.85,503 1203.76,503 1203.76,787.8 1029.76,787.8 1000.36,787.8 1000.36,503.49 ; 1589.76,876.8 1874.76,876.8 1874.76,1080 1589.76,1080 1589.76,876.8
  text ".Layer_Name" at 576.96,-1164 h60
Top Paste:
  text ".Layer_Name" at 576.96,-1164 h60
Bottom Paste:
  text ".Layer_Name" at 576.96,-1164 h60
Top Solder:
  text ".Layer_Name" at 576.96,-1164 h60
  text ".Layer_Name" at 576.96,-1164 h60
Bottom Solder:
  text ".Layer_Name" at 576.96,-1164 h60
Drill Guide:
  text ".Layer_Name" at 576.96,-1164 h60
M1 Board Outline:
  the board outline again, w10
M2 Board Dimensions:
  rectangle: -0.04,-580.51 124.96,-455.51
  rectangle: 124.96,-705.51 499.96,-580.51
  lines w7: -0.04,-580.51 999.96,-580.51 ; 124.96,-705.51 124.96,-455.51 ; 249.96,-705.51 249.96,-455.51 ; 499.96,-705.51 499.96,-455.51 ; 749.96,-705.51 749.96,-455.51 ; -0.04,-705.51 999.96,-705.51 999.96,-455.51 -0.04,-455.51 -0.04,-705.51
M3 3D STEP Top:
  text ".Layer_Name" at 576.96,-1164 h60
M4 3D STEP Bottom:
  text ".Layer_Name" at 576.96,-1164 h60
M5 Assembly Top:
  circle w6: c1060.76,400.8 r7.07
  lines w10: -292.04,-1235.68 6307.96,-1235.68 ; -292.04,-1032.34 6309.96,-1032.34 ; -292.04,-829.01 -292.04,-1439.01 3712.96,-1439.01 6309.96,-1439.01 6309.96,-829.01 -291.54,-829.01 -291.54,-1439.01 1283.96,-1439.01 ; 2172.96,-1439.01 2172.96,-829.01 ; 3439.96,-1032.34 3439.96,-829.01 ; 4279.96,-1032.34 4279.96,-829.01 ; 4901.96,-1445.51 4901.96,-1242.68
  text "1" at 616,107 h40
  text "1" at 34,104 h40
  text "1" at 1592,104 h40
  text "COMPONENTS MARKED 'DNP' SHOULD NOT BE POPULATED." at 1153.46,-624.01 h60
  text "ASSEMBLY VARIANT:" at 1152.96,-739.51 h60
  text ".VariantName" at 2188.96,-739.51 h60
  text "PCB VIEWED FROM TOP SIDE" at -228.54,-961.18 h60
  text "BOARD #:" at 2247.96,-961.18 h60
  text ".PRJ_Number" at 2793.46,-961.18 h60
  text "REV:" at 3637.96,-961.18 h60
  text ".PCB_Rev" at 3929.46,-961.18 h60
  text "SVN REV:" at 4475.96,-961.18 h60
  text ".VersionControl_RevNumber" at 4981.96,-961.18 h60
  text ".LAyer_Name" at 576.26,-1161 h60
  text "TID #:" at 2247.96,-1164.51 h60
  text ".TID" at 2793.46,-1164.51 h60
  text "PLOT NAME =" at -228.54,-1369.85 h60
  text ".plot_File_Name" at 576.96,-1369.85 h60
  text "GENERATED    :" at 2249.96,-1369.85 h60
  text ".Print_Date" at 3119.46,-1369.85 h60
  text ".Print_Time" at 3848.46,-1369.85 h60
  text "TEXAS INSTRUMENTS" at 5112.96,-1369.85 h60
M6 Assembly Bottom:
  circle w6: c493,127 r6
  circle w6: c1213.76,734.8 r7.28
  circle w6: c1567.76,1026.8 r8
  circle w6: c282.17,655.91 r5.1
  lines w10: -292.54,-1032.84 6309.46,-1032.84 ; -290.54,-1236.18 6309.46,-1236.18 ; 1115.46,-1446.01 1115.46,-1243.18 ; 1737.46,-1032.84 1737.46,-829.51 ; 2577.46,-1032.84 2577.46,-829.51 ; 3844.46,-1439.51 3844.46,-829.51 ; 4733.46,-1439.51 6308.96,-1439.51 6308.96,-829.51 -292.54,-829.51 -292.54,-1439.51 2304.46,-1439.51 6309.46,-1439.51 6309.46,-829.51 ; 173.26,641.1 174.26,640.1 298.7,640.1 299.26,640.67 299.26,883.1 173.26,883.1 173.26,876.1 173.26,641.1
  text "COMPONENTS MARKED 'DNP' SHOULD NOT BE POPULATED." at 6101.96,-623.51 h60
  text ".VariantName" at 5057.96,-739.51 h60
  text "ASSEMBLY VARIANT:" at 6096.96,-739.51 h60
  text ".VersionControl_RevNumber" at 1035.46,-961.68 h60
  text "SVN REV:" at 1541.46,-961.68 h60
  text ".PCB_Rev" at 2087.96,-961.68 h60
  text "REV:" at 2379.46,-961.68 h60
  text ".PRJ_Number" at 3223.96,-961.68 h60
  text "BOARD #:" at 3769.46,-961.68 h60
  text "PCB VIEWED FROM BOTTOM SIDE" at 6245.96,-961.68 h60
  text ".LAyer_Name" at 5516.96,-1150 h60
  text ".TID" at 3223.96,-1165.01 h60
  text "TID #:" at 3769.46,-1165.01 h60
  text "TEXAS INSTRUMENTS" at 904.46,-1370.35 h60
  text ".Print_Time" at 2168.96,-1370.35 h60
  text ".Print_Date" at 2897.96,-1370.35 h60
  text "GENERATED    :" at 3767.46,-1370.35 h60
  text ".plot_File_Name" at 5440.46,-1370.35 h60
  text "PLOT NAME =" at 6245.96,-1370.35 h60
M9 Title Sheet:
  drawing of 57 lines, arcs and shapes, not listed
  text "1" at 739.8,7730.99 h70
  text "2" at 3235.46,7730.99 h70
  text "3" at 5724.8,7730.99 h70
  text "4" at 8231.47,7730.99 h70
  text "5" at 10730.46,7730.99 h70
  text "6" at 13235.46,7730.99 h70
  text "A" at -416.54,6587.99 h70
  text "A" at 14383.46,6587.99 h70
  text "B" at -416.54,4207.99 h70
  text "B" at 14383.46,4207.99 h70
  text "C" at -416.54,1832.99 h70
  text "C" at 14383.46,1832.99 h70
  text "PROJECT TITLE:" at 11343.46,-28.01 h45
  text ".PRJ_Title" at 11393.46,-161.34 h70
  text "DESIGNED FOR:" at 11343.46,-329.01 h45
  text ".PRJ_Customer" at 11393.46,-469.01 h70
  text "D" at -416.54,-537.01 h70
  text "D" at 14383.46,-537.01 h70
  text "FILE NAME:" at 11343.46,-629.01 h45
  text ".PCB_File_Name_No_Path" at 11393.46,-749.01 h70
  text "Texas Instruments (TI) and/or its licensors do not warrant the accuracy or completeness of this specification" at 6373.96,-910.85 h45
  text "ENGINEER:" at 11343.46,-919.01 h45
  text "LAYOUT BY:" at 12848.46,-919.01 h45
  text "or any information contained therein. TI and/or its licensors do not warrant that this design will meet" at 6328.98,-1023.51 h45
  text ".PRJ_Engineer" at 11393.46,-1074 h70
  text ".PCB_Layout" at 12898.96,-1074 h70
  text "the specifications, will be suitable for your application or fit for any particular purpose, or will operate in" at 6328.98,-1136.18 h45
  text "ALTIUM DESIGNER VERSION:" at 12848.46,-1229.01 h45
  text "an implementation. TI and/or its licensors do not warrant that the design is production worthy. You should" at 6328.98,-1248.85 h45
  text "completely validate and test your design implementation to confirm the system functionality for your application." at 6373.96,-1361.51 h45
  text ".print_Scale" at 11393.46,-1362.34 h70
  text ".Application_BuildNumber" at 12898.96,-1362.34 h70
  text "1" at 739.8,-1569.01 h70
  text "2" at 3235.46,-1569.01 h70
  text "3" at 5724.8,-1569.01 h70
  text "4" at 8231.47,-1569.01 h70
  text "5" at 10730.46,-1569.01 h70
  text "6" at 13235.46,-1569.01 h70
M10 Fab Notes:
  drawing of 191 lines, arcs and shapes, not listed
  text "DESIGN INFORMATION" at 12386.48,6384.49 h60
  text "(REFER ALSO ARRAY/PANEL PROFILING INFORMATION)" at 12024.92,6222.77 h60
  text "BOARD SIZE" at 11338.92,6218.49 h60
  text "X" at 12306.92,6090.67 h60
  text "40MM" at 12542.46,6083.49 h60
  text "48MM" at 11854.96,6080 h60
  text "Number of Layers :" at 11756.92,5983.49 h60
  text "2" at 12851.73,5973.49 h60
  text "MIN. TRACK WIDTH:" at 11756.92,5844.49 h60
  text "10" at 12826.46,5844.89 h60
  text "MIL" at 13007.92,5844.49 h60
  text "MIN. CLEARANCE:" at 11756.92,5712.49 h60
  text "7.87" at 12774.96,5712 h60
  text "MIL" at 13025.46,5685.89 h60
  text "MIN. VIA PAD SIZE:" at 11756.92,5580.49 h60
  text "30" at 12837.46,5580.89 h60
  text "MIL" at 13025.46,5557.89 h60
  text "0.19mm (7.5MIL)" at 12451.92,5438.78 h60
  text "EXTERNAL" at 13188.46,5438.89 h60
  text "MINIMUM ANNULAR RING" at 11427.69,5434.49 h60
  text "PER" at 11627.69,5316.49 h60
  text "IPC-D-275 CLASS 2 LEVEL C" at 11847.69,5316.49 h60
  text "MIL, HOLES" at 13335.92,5204.2 h60
  text "+/-" at 12943.46,5203.49 h60
  text "+/-" at 13797.46,5203.49 h60
  text "REGISTRATION TOLERANCES:" at 11427.69,5198.49 h60
  text "METAL" at 12627.46,5198.49 h60
  text "5" at 13203.66,5198.49 h60
  text "3" at 14036.66,5198.49 h60
  text "MIL" at 14152.92,5198.49 h60
  text "IMPEDENCE CONTROLLED BOARD:NO" at 11460.46,5049.49 h60
  text "MATERIAL:" at 11336.92,4826.03 h60
  text "FR-4 High Tg" at 12323.36,4685.7 h60
  text "FR-408" at 11757.92,4677.13 h60
  text "OTHER" at 13245.92,4677.13 h60
  text "X" at 12161.46,4675.49 h60
  text "THICKNESS:" at 11338.46,4520.49 h60
  text "63 MIL (1.6mm) +/-10%" at 11997.46,4515.49 h60
  text "OTHER" at 13362.92,4510.13 h60
  text "X" at 11862.46,4507.49 h60
  text "TOLERANCE:" at 11411.69,4352.13 h60
  text "X" at 12251,4352.13 h60
  text "ANSI IPC-6012 TYPE 3 CLASS 2" at 12437.94,4352.13 h60
  text "OTHER +/-" at 12437.92,4196.13 h60
  text "BOW & TWIST:" at 11411.69,4039.13 h60
  text "X" at 12251,4039.13 h60
  text "ANSI IPC-6012 TYPE 3 CLASS 2" at 12437.94,4039.13 h60
  text "OTHER +/-" at 12437.92,3880.62 h60
  text "DRILLING:" at 11336.92,3742.13 h60
  text "REFERENCE:" at 11411.69,3625.13 h60
  text "X" at 12059.92,3625.13 h60
  text "AS SHOWN" at 12246.92,3625.13 h60
  text "X" at 12960.92,3625.13 h60
  text "NC_DRILL FILES" at 13097.92,3625.13 h60
  text "PTH MIN COPPER THICKNESS:" at 11411.69,3467.13 h60
  text "X" at 12761.92,3467.13 h60
  text "1MIL" at 12898.92,3467.13 h60
  text "OTHER" at 13395.92,3467.13 h60
  text "BOARD FINISH:" at 11336.92,3308.13 h60
  text "SILKSCREEN:" at 11492.14,3190.13 h60
  text "X" at 12440.92,3190.13 h60
  text "TOP" at 12566.92,3190.13 h60
  text "X" at 12950.92,3190.13 h60
  text "BOTTOM" at 13077.92,3190.13 h60
  text "SILKSCREEN COLOR:" at 11492.14,3023.13 h60
  text "X" at 12439.88,3023.13 h60
  text "WHITE" at 12566.92,3023.13 h60
  text "OTHER" at 13077.92,3023.13 h60
  text "SOLDER RESIST COLOR:" at 11492.14,2853.13 h60
  text "X" at 12059.88,2693.93 h60
  text "GREEN" at 12186.92,2693.93 h60
  text "BLUE" at 12777.92,2693.93 h60
  text "OTHER" at 13315.92,2693.93 h60
  text "IMMERSION GOLD (ENIG)" at 12397.92,2505.41 h60
  text "ENEPIG" at 13735.46,2502.13 h60
  text "SURFACE FINISH:" at 11336.92,2501.13 h60
  text "X" at 12210.97,2501.13 h60
  text "IMM. TIN/SILVER OR EQUIV" at 11666.46,2344.13 h60
  text "OTHER" at 13097.92,2344.13 h60
  text "ARRAY/PANEL:" at 11336.92,2165.13 h60
  text "CUT AND TRIM PER MECH LAYER 1" at 12397.92,2160.84 h60
  text "N.C. ROUTE" at 12397.92,2009.13 h60
  text "X" at 13076.92,2009.13 h60
  text "V. SCORE" at 13263.92,2009.13 h60
  text "CERTIFICATION:" at 11336.92,1872.13 h60
  text "MATERIALS AND WORKMANSHIP FOR ALL PCBS" at 12061.92,1872.13 h60
  text "TO MEET OR EXCEED THE REQUIREMENTS OF:" at 12061.92,1774.13 h60
  text "X" at 11688.42,1637.62 h60
  text "ANSI IPC-A-600F CLASS ->" at 11827.42,1637.62 h60
  text "X" at 13466.48,1637.62 h60
  text "2" at 13585.42,1637.62 h60
  text "1" at 13270.42,1636.13 h60
  text "3" at 13939.42,1636.13 h60
  text "X" at 11690.48,1478.13 h60
  text "UL 94V-0" at 11827.42,1478.13 h60
  text "X" at 12502.48,1478.13 h60
  text "RoHS" at 12639.42,1478.13 h60
  text "OTHER" at 13283.83,1478.13 h60
  text "PER ORDER" at 13680.88,1478.13 h60
  text "ADDITIONAL REQUIREMENTS:" at 11336.92,1337.13 h60
  text "MICROSECTION:" at 11411.69,1222.13 h60
  text "YES" at 12317.42,1222.13 h60
  text "REQUIRED" at 13178.92,1065.98 h60
  text "BARE BOARD ELEC. TEST:" at 11411.69,1063.13 h60
  text "NONE" at 12717.42,1063.13 h60
  text "X" at 13051.92,1063.13 h60
  text "PER ORDER" at 13770.92,1063.13 h60
  text "MANUFACTURER'S UL:" at 11411.69,906.13 h60
  text "RAIL" at 12577.42,901.84 h60
  text "METAL" at 13069.24,901.84 h60
  text "X" at 13444.46,901.49 h60
  text "SILK" at 13580.92,901.84 h60
  text "VIA`S TO BE TENTED:" at 11391.46,714.49 h60
  text "NO" at 12296.46,714.49 h60
M11 Gerber Information:
  lines w10: -292.04,-1235.68 6307.96,-1235.68 ; -292.04,-1032.34 6309.96,-1032.34 ; -292.04,-829.01 -292.04,-1439.01 3712.96,-1439.01 6309.96,-1439.01 6309.96,-829.01 -291.54,-829.01 -291.54,-1439.01 1283.96,-1439.01 ; 2172.96,-1439.01 2172.96,-829.01 ; 3439.96,-1032.34 3439.96,-829.01 ; 4279.96,-1032.34 4279.96,-829.01 ; 4901.96,-1445.51 4901.96,-1242.68
  text "ALL ARTWORK VIEWED FROM TOP SIDE" at -228.54,-961.18 h60
  text "BOARD #:" at 2247.96,-961.18 h60
  text ".PRJ_Number" at 2793.46,-961.18 h60
  text "REV:" at 3637.96,-961.18 h60
  text ".PCB_Rev" at 3929.46,-961.18 h60
  text "SVN REV:" at 4475.96,-961.18 h60
  text ".VersionControl_RevNumber" at 4981.96,-961.18 h60
  text "LAYER NAME =" at -228.54,-1164 h60
  text "TID #:" at 2247.96,-1164.51 h60
  text ".TID" at 2793.46,-1164.51 h60
  text "PLOT NAME =" at -228.54,-1369.85 h60
  text ".plot_File_Name" at 576.96,-1369.85 h60
  text "GENERATED    :" at 2249.96,-1369.85 h60
  text ".Print_Date" at 3119.46,-1369.85 h60
  text ".Print_Time" at 3848.46,-1369.85 h60
  text "TEXAS INSTRUMENTS" at 5112.96,-1369.85 h60
M12 Stackup:
  drawing of 191 lines, arcs and shapes, not listed
  text "Layer" at 9741.96,7459 h60
  text "Name" at 10151.87,7459 h60
  text "Material" at 11081.62,7459 h60
  text "Thickness" at 11941.39,7459 h60
  text "Constant" at 12591.22,7459 h60
  text "Board Layer Stack" at 13161.08,7459 h60
  text "1" at 9741.96,7339 h60
  text "Top Overlay" at 10151.87,7339 h60
  text "2" at 9741.96,7219 h60
  text "Top Solder" at 10151.87,7219 h60
  text "Solder Resist" at 11081.62,7219 h60
  text "0.40mil" at 11941.39,7219 h60
  text "3.5" at 12591.22,7219 h60
  text "3" at 9741.96,7099 h60
  text "Top Layer" at 10151.87,7099 h60
  text "Copper" at 11081.62,7099 h60
  text "2.80mil" at 11941.39,7099 h60
  text "4" at 9741.96,6979 h60
  text "Dielectric1" at 10151.87,6979 h60
  text "FR-4 High Tg" at 11081.62,6979 h60
  text "59.20mil" at 11941.39,6979 h60
  text "4.8" at 12591.22,6979 h60
  text "5" at 9741.96,6859 h60
  text "Bottom Layer" at 10151.87,6859 h60
  text "Copper" at 11081.62,6859 h60
  text "2.80mil" at 11941.39,6859 h60
  text "6" at 9741.96,6739 h60
  text "Bottom Solder" at 10151.87,6739 h60
  text "Solder Resist" at 11081.62,6739 h60
  text "0.40mil" at 11941.39,6739 h60
  text "3.5" at 12591.22,6739 h60
  text "7" at 9741.96,6619 h60
  text "Bottom Overlay" at 10151.87,6619 h60
M13 Component Bodies Top:
  text ".Layer_Name" at 576.96,-1164 h60
M14 Component Bodies Bottom:
  text ".Layer_Name" at 576.96,-1164 h60
M15 Courtyards Top:
  text ".Layer_Name" at 576.96,-1164 h60
M16 Courtyards Bottom:
  text ".Layer_Name" at 576.96,-1164 h60
Drill Drawing:
  circle w10: c4868.12,1872 r25
  lines w10: 4843.12,2047 4893.12,2047 4868.12,1997 4843.12,2047 ; 4843.12,2147 4893.12,2147 4893.12,2197 4843.12,2197 4843.12,2147 ; 4843.12,2297 4893.12,2297 4893.12,2347 4843.12,2347 4843.12,2297 ; 4843.12,2459.5 4855.62,2459.5 4855.62,2447 4880.62,2447 4880.62,2459.5 4893.12,2459.5 4893.12,2484.5 4880.62,2484.5 4880.62,2497 4855.62,2497 4855.62,2484.5 4843.12,2484.5 4843.12,2459.5 ; 4843.12,2647 4893.12,2647 4868.12,2597 4843.12,2647 ; 4843.12,2759.5 4855.62,2759.5 4868.12,2747 4880.62,2759.5 4893.12,2759.5 4880.62,2772 4893.12,2784.5 4880.62,2784.5 4868.12,2797 4855.62,2784.5 4843.12,2784.5 4855.62,2772 4843.12,2759.5 ; 4853.12,2157 4883.12,2157 4883.12,2187 4853.12,2187 4853.12,2157 ; 4853.12,2637 4883.12,2637 4868.12,2607 4853.12,2637 ; 4853.12,2764.5 4860.62,2764.5 4868.12,2757 4875.62,2764.5 4883.12,2764.5 4875.62,2772 4883.12,2779.5 4875.62,2779.5 4868.12,2787 4860.62,2779.5 4853.12,2779.5 4860.62,2772 4853.12,2764.5
  lines w15: 4775,1802 8653.97,1802 ; 4775,2852 8653.97,2852 ; 5325.88,1652 5325.88,3002 ; 6023.69,1652 6023.69,3002 ; 7369.29,1652 7369.29,3002 ; 7875.17,1652 7875.17,3002 ; 4775,1652 8653.97,1652 8653.97,3002 4775,3002 4775,1652
  text "Symbol" at 4865,2897 h72
  text "Hit Count" at 5370.88,2897 h72
  text "Finished Hole Size" at 6068.69,2897 h72
  text "Plated" at 7414.29,2897 h72
  text "Hole Type" at 7920.17,2897 h72
  text "2" at 5370.88,2747 h60
  text "28.00mil (0.711mm)" at 6068.69,2747 h60
  text "PTH" at 7414.29,2747 h60
  text "Round" at 7920.17,2747 h60
  text "2" at 5370.88,2597 h60
  text "33.46mil (0.850mm)" at 6068.69,2597 h60
  text "PTH" at 7414.29,2597 h60
  text "Round" at 7920.17,2597 h60
  text "2" at 5370.88,2447 h60
  text "37.40mil (0.950mm)" at 6068.69,2447 h60
  text "PTH" at 7414.29,2447 h60
  text "Round" at 7920.17,2447 h60
  text "4" at 5370.88,2297 h60
  text "31.00mil (0.787mm)" at 6068.69,2297 h60
  text "PTH" at 7414.29,2297 h60
  text "Round" at 7920.17,2297 h60
  text "6" at 5370.88,2147 h60
  text "51.18mil (1.300mm)" at 6068.69,2147 h60
  text "PTH" at 7414.29,2147 h60
  text "Round" at 7920.17,2147 h60
  text "10" at 5370.88,1997 h60
  text "46.06mil (1.170mm)" at 6068.69,1997 h60
  text "PTH" at 7414.29,1997 h60
  text "Round" at 7920.17,1997 h60
  text "115" at 5370.88,1847 h60
  text "15.00mil (0.381mm)" at 6068.69,1847 h60
  text "PTH" at 7414.29,1847 h60
  text "Round" at 7920.17,1847 h60
  text "141 Total" at 5370.88,1697 h60
  text "DRILL TABLE" at 5522.96,1499 h60
  text "FOR 15MIL DRILL +0/-15MIL" at 5519.76,1401.8 h60
  text "FOR PTH +3/-3MIL" at 5522.76,1308.8 h60
  text "Copper thickness is 2oz." at 5518.76,1215.8 h60
  text ".Layer_Name" at 576.96,-1164 h60

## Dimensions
0,0 to 0,1574.8 on M2 Board Dimensions
0,0 to 1889.76,0 on M2 Board Dimensions
-0.04,-705.51 to 999.96,-705.51 on M2 Board Dimensions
